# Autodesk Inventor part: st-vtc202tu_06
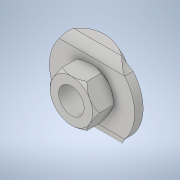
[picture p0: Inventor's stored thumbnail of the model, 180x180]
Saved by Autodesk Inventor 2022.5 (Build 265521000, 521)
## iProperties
Created: 2021-08
Part Number: st-vtc202tu_06
Material: 一般
Document SubType Name: Modeling
Designer: ImaoCorp
Density: 1 g/cm^3
Appearance: 既定
Author: ImaoCorp
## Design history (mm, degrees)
feature "st-vtc202tu_06"
node "ソリッド1"
